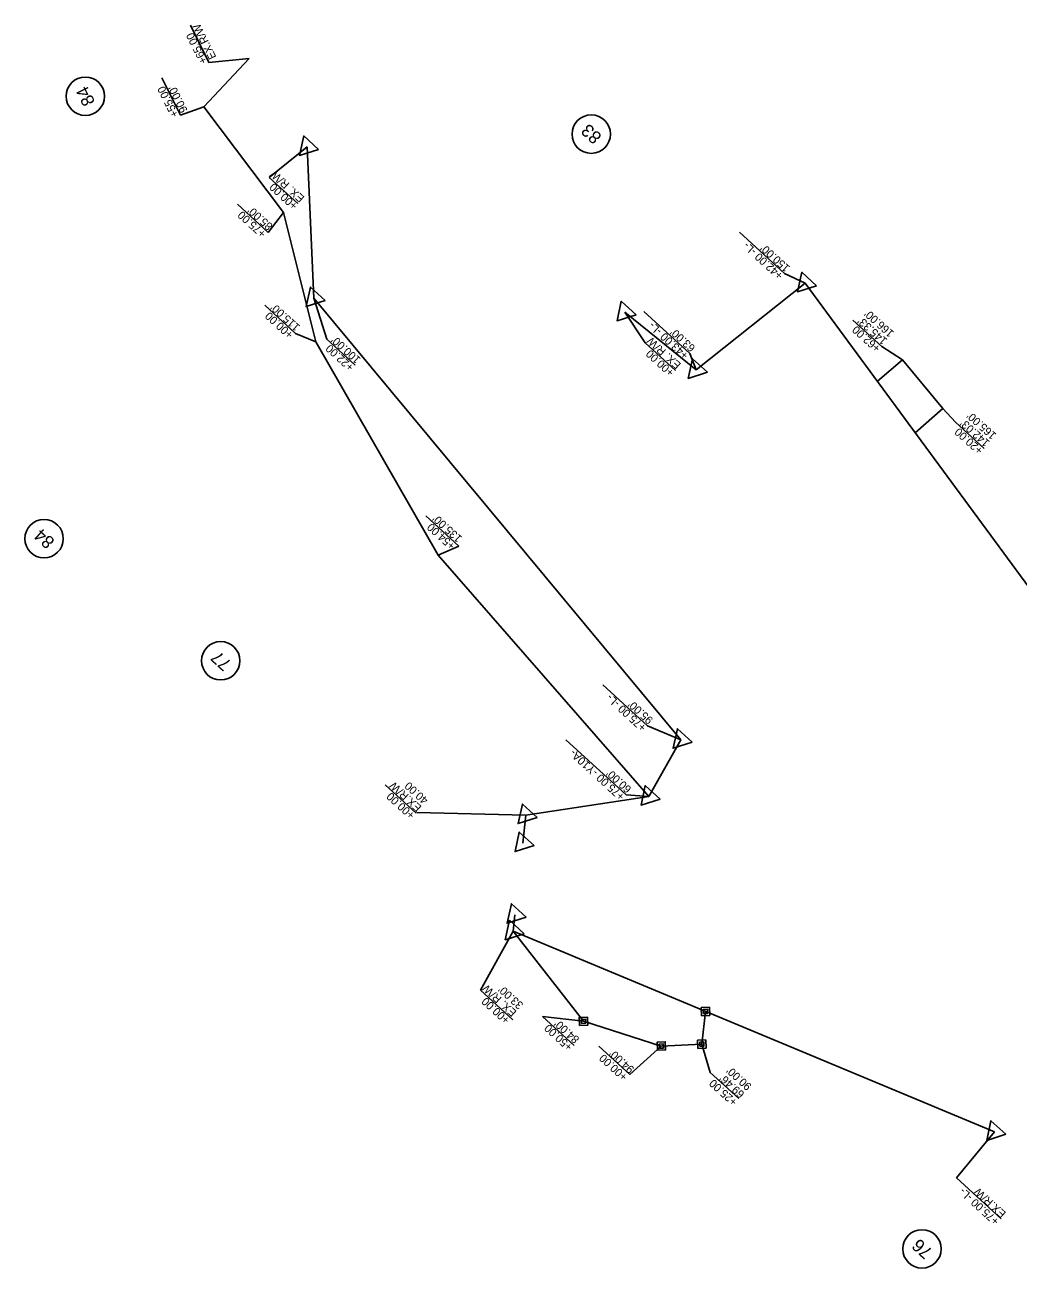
# Model space of a CAD drawing. Extents: x 474184 to 481900, y 489262 to 505659.
# Drawn here: x 476024 to 476644, y 500477 to 501253 of the extents above; entities that cross this region are included whole.
import ezdxf

# ---------------------------------------------------------------- set-up
doc = ezdxf.new("R2010")
doc.units = 0
for name, color, linetype in [('Prop Drainage Structure Drop Inlet Grate 2 Wide Slots and Sag Grates 840 22 CELL', 7, 'Continuous'), ('Prop Drainage Structure Pipe CSP 15in', 7, 'Continuous'), ('Prop Drainage Structure Pipe RCP 18in Class IV', 7, 'Continuous'), ('Prop Drainage Structure Pipe RCP 18in Class IV Label', 7, 'Continuous'), ('Prop Drainage Structure Pipe Side Drain 15in Label', 7, 'Continuous'), ('Prop Drainage Structure Pipe Stub Out CELL', 7, 'Continuous'), ('Prop Drainage Structure Plot Symbol 50 Scale', 7, 'Continuous'), ('Prop Earthen Structure False Sump CELL', 7, 'Continuous'), ('Prop Earthen Structure False Sump Label', 7, 'Continuous')]:
    doc.layers.add(name, color=color, linetype=linetype)

msp = doc.modelspace()

# ---------------------------------------------------------------- linework, layer by layer
at = {"layer": 'Prop Drainage Structure Drop Inlet Grate 2 Wide Slots and Sag Grates 840 22 CELL'}
for p, q in [((476372.78, 500631.1), (476328.73, 500687.32)), ((476446.66, 500616.85), (476448.93, 500637.26)), ((476421.37, 500615.64), (476372.78, 500631.1)), ((476446.66, 500616.85), (476421.37, 500615.64))]:
    msp.add_line(p, q, dxfattribs=at)
at = {"layer": 'Prop Drainage Structure Pipe CSP 15in'}
for p, q in [((476061.59, 501208.84), (476061.59, 501208.84)), ((476377.59, 501185.16), (476377.59, 501185.16)), ((476035.83, 500932.5), (476035.83, 500932.5)), ((476146.17, 500856.26), (476146.17, 500856.26)), ((476584.17, 500488.95), (476584.17, 500488.95))]:
    msp.add_line(p, q, dxfattribs=at)
for centre in [(476061.59, 501208.84), (476377.59, 501185.16), (476035.83, 500932.5), (476146.17, 500856.26), (476584.17, 500488.95)]:
    msp.add_circle(centre, 12, dxfattribs=at)
at = {"layer": 'Prop Drainage Structure Pipe RCP 18in Class IV'}
for p, q in [((476200.18, 501177.17), (476200.18, 501177.17)), ((476511.26, 501092.03), (476511.26, 501092.03)), ((476204.38, 501082.76), (476204.38, 501082.76)), ((476398.57, 501073.95), (476398.57, 501073.95)), ((476443.09, 501037.97), (476443.09, 501037.97)), ((476433.59, 500806.92), (476433.59, 500806.92)), ((476413.55, 500771.46), (476413.55, 500771.46)), ((476336.8, 500759.87), (476336.8, 500759.87)), ((476334.86, 500742.41), (476334.86, 500742.41)), ((476329.88, 500697.69), (476329.88, 500697.69)), ((476328.73, 500687.32), (476328.73, 500687.32)), ((476448.93, 500637.26), (476448.93, 500637.26)), ((476372.78, 500631.1), (476372.78, 500631.1)), ((476421.37, 500615.64), (476421.37, 500615.64)), ((476446.66, 500616.85), (476446.66, 500616.85)), ((476629.46, 500562.08), (476629.46, 500562.08))]:
    msp.add_line(p, q, dxfattribs=at)
for points in [[(476207.22, 501175.62), (476195.32, 501171.86), (476197.99, 501184.05)], [(476518.3, 501090.47), (476506.4, 501086.71), (476509.08, 501098.9)], [(476211.42, 501081.2), (476199.52, 501077.44), (476202.19, 501089.63)], [(476405.61, 501072.39), (476393.71, 501068.63), (476396.38, 501080.82)], [(476450.13, 501036.41), (476438.23, 501032.65), (476440.9, 501044.84)], [(476440.63, 500805.36), (476428.73, 500801.6), (476431.4, 500813.79)], [(476420.59, 500769.9), (476408.69, 500766.14), (476411.36, 500778.33)], [(476343.84, 500758.31), (476331.94, 500754.56), (476334.61, 500766.74)], [(476341.9, 500740.85), (476330, 500737.1), (476332.67, 500749.29)], [(476336.92, 500696.13), (476325.02, 500692.37), (476327.7, 500704.56)], [(476335.77, 500685.76), (476323.87, 500682), (476326.54, 500694.19)], [(476636.5, 500560.52), (476624.6, 500556.76), (476627.28, 500568.95)]]:
    msp.add_lwpolyline(points, close=True, dxfattribs=at)
at = {"layer": 'Prop Drainage Structure Pipe RCP 18in Class IV Label'}
for points in [[(476370.36, 500628.45), (476370.13, 500633.53), (476375.21, 500633.76), (476375.44, 500628.68)], [(476446.5, 500634.6), (476446.27, 500639.69), (476451.36, 500639.92), (476451.59, 500634.83)], [(476447.72, 500635.93), (476447.6, 500638.47), (476450.14, 500638.59), (476450.26, 500636.05)], [(476371.57, 500629.77), (476371.45, 500632.32), (476374, 500632.43), (476374.11, 500629.89)], [(476418.94, 500612.98), (476418.71, 500618.07), (476423.8, 500618.29), (476424.03, 500613.21)], [(476444.23, 500614.19), (476444, 500619.28), (476449.09, 500619.51), (476449.32, 500614.42)], [(476445.45, 500615.52), (476445.33, 500618.06), (476447.87, 500618.18), (476447.99, 500615.63)], [(476420.16, 500614.31), (476420.04, 500616.85), (476422.59, 500616.97), (476422.7, 500614.42)]]:
    msp.add_lwpolyline(points, close=True, dxfattribs=at)
at = {"layer": 'Prop Drainage Structure Pipe Side Drain 15in Label'}
for p, q in [((476204.38, 501082.76), (476200.18, 501177.17)), ((476511.26, 501092.03), (476443.09, 501037.97)), ((476740.27, 500780.72), (476511.26, 501092.03)), ((476433.59, 500806.92), (476204.38, 501082.76)), ((476398.57, 501073.95), (476443.09, 501037.97)), ((476413.55, 500771.46), (476433.59, 500806.92)), ((476413.55, 500771.46), (476336.8, 500759.87)), ((476334.86, 500742.41), (476336.8, 500759.87)), ((476328.73, 500687.32), (476329.88, 500697.69)), ((476629.46, 500562.08), (476328.73, 500687.32))]:
    msp.add_line(p, q, dxfattribs=at)
at = {"layer": 'Prop Drainage Structure Pipe Stub Out CELL'}
for p, q in [((476135.58, 501202.12), (476163.83, 501232.42)), ((476185.36, 501136.21), (476135.58, 501202.12)), ((476205.5, 501055.47), (476185.36, 501136.21)), ((476282.06, 500922.22), (476205.5, 501055.47)), ((476571.98, 501044.26), (476556.3, 501030.8)), ((476597.23, 501013.78), (476571.98, 501044.26)), ((476580.02, 500998.56), (476597.23, 501013.78)), ((476413.55, 500771.46), (476282.06, 500922.22))]:
    msp.add_line(p, q, dxfattribs=at)
at = {"layer": 'Prop Drainage Structure Plot Symbol 50 Scale'}
for p, q in [((476176.52, 501158.1), (476200.18, 501177.17)), ((476176.52, 501158.1), (476194.27, 501141.88)), ((476470.12, 501123.93), (476498.36, 501098.12)), ((476212.49, 501057.03), (476204.38, 501082.76)), ((476411.31, 501054.75), (476398.57, 501073.95)), ((476410.52, 501074.31), (476439.2, 501048.1)), ((476212.49, 501057.03), (476230.24, 501040.81)), ((476411.31, 501054.75), (476430.24, 501037.45)), ((476439.2, 501048.1), (476443.09, 501037.97)), ((476384.76, 500841.33), (476412.83, 500815.67)), ((476361.72, 500806.93), (476399.31, 500772.58)), ((476248.94, 500778.87), (476268.33, 500761.15)), ((476308.37, 500650.6), (476328.67, 500632.05)), ((476605.7, 500533.27), (476629.46, 500562.08)), ((476605.7, 500533.27), (476633.69, 500507.69))]:
    msp.add_line(p, q, dxfattribs=at)
for points in [[(476498.36, 501098.12), (476511.26, 501092.03)], [(476412.83, 500815.67), (476433.59, 500806.92)], [(476399.31, 500772.58), (476413.55, 500771.46)], [(476268.62, 500761.47), (476336.8, 500759.87)], [(476308.37, 500650.6), (476328.73, 500687.32)]]:
    msp.add_lwpolyline(points, dxfattribs=at)
at = {"layer": 'Prop Earthen Structure False Sump CELL'}
for p, q in [((476347.22, 500634.1), (476367.03, 500615.99)), ((476382.3, 500615.54), (476401.72, 500597.8)), ((476401.72, 500597.8), (476421.37, 500615.64)), ((476451.83, 500599.18), (476446.66, 500616.85)), ((476451.83, 500599.18), (476469.68, 500582.87))]:
    msp.add_line(p, q, dxfattribs=at)
msp.add_lwpolyline([(476347.22, 500634.1), (476372.78, 500631.1)], dxfattribs=at)
at = {"layer": 'Prop Earthen Structure False Sump Label'}
for p, q in [((476127.24, 501253.27), (476138.83, 501229.97)), ((476163.83, 501232.42), (476138.83, 501229.97)), ((476109.4, 501220.32), (476120.99, 501197.02)), ((476120.99, 501197.02), (476135.58, 501202.12)), ((476156.58, 501141.36), (476175.79, 501123.8)), ((476185.36, 501136.21), (476175.79, 501123.8)), ((476173.65, 501078.31), (476192.86, 501060.75)), ((476559.07, 501052.59), (476541.04, 501069.06)), ((476205.5, 501055.47), (476192.86, 501060.75)), ((476571.98, 501044.26), (476559.07, 501052.59)), ((476597.23, 501013.78), (476605.03, 501005.28)), ((476623.06, 500988.8), (476605.03, 501005.28)), ((476274.3, 500946.69), (476294.98, 500927.8)), ((476294.98, 500927.8), (476282.06, 500922.22))]:
    msp.add_line(p, q, dxfattribs=at)

# ---------------------------------------------------------------- texts
at = {"layer": 'Prop Drainage Structure Pipe CSP 15in'}
for s, rotation, p in [('84', 116.44074, (476067.86, 501205.21)), ('83', 137.57996, (476384.66, 501184.13)), ('84', 137.57996, (476042.99, 500931.38)), ('77', 137.57996, (476153.39, 500855.08)), ('76', 137.71823, (476591.31, 500487.86))]:
    msp.add_text(s, height=8, rotation=rotation, dxfattribs=at).set_placement(p)
at = {"layer": 'Prop Drainage Structure Plot Symbol 50 Scale'}
for s, p in [('EX. R/W', (476198.86, 501145.72)), ('+00.00', (476194.64, 501141.11)), ('+42.00 -L-', (476497.83, 501097.54)), ("150.00'", (476502.05, 501102.16)), ('+43.00 -L-', (476438.78, 501047.64)), ("63.00'", (476443, 501052.25)), ('+22.00', (476229.76, 501040.29)), ("100.00'", (476233.97, 501044.9)), ('EX. R/W', (476434.03, 501041.6)), ('+00.00', (476429.82, 501036.99)), ('+75.00 -L-', (476412.41, 500815.21)), ("95.00'", (476416.62, 500819.82)), ('+75.00 -Y10A-', (476398.89, 500772.12)), ('EX.R/W ', (476271.99, 500765.16)), ('40.00', (476276.21, 500769.77)), ("60.00'", (476403.1, 500776.73)), ('+00.00', (476267.78, 500760.54)), ('EX. R/W', (476331.38, 500637.18)), ("33.00'", (476335.6, 500641.79)), ('+00.00', (476327.17, 500632.57)), ('+75.00 -L-', (476632.83, 500506.89)), ('EX.R/W', (476637.05, 500511.51))]:
    msp.add_text(s, height=5, rotation=137.57996, dxfattribs=at).set_placement(p)
at = {"layer": 'Prop Earthen Structure False Sump CELL'}
for s, p in [('+50.00', (476366.33, 500615.79)), ("84.00'", (476370.55, 500620.4)), ('+00.00', (476400.65, 500597.11)), ("94.00'", (476404.86, 500601.73)), ("90.00'", (476478.15, 500591.07)), ('+25.00', (476469.31, 500581.39)), ("69.46'", (476473.73, 500586.23))]:
    msp.add_text(s, height=5, rotation=137.57996, dxfattribs=at).set_placement(p)
at = {"layer": 'Prop Earthen Structure False Sump Label'}
for s, rotation, p in [('+65.00', 116.44074, (476137.95, 501230.57)), ('EX.R/W', 116.44074, (476143.55, 501233.35)), ('+55.00', 116.44074, (476120.04, 501197.22)), ("90.00'", 116.44074, (476125.64, 501200)), ("85.00'", 137.57996, (476179.05, 501128.26)), ('+75.00', 137.57996, (476174.83, 501123.65)), ("115.00'", 137.57996, (476196.12, 501065.21)), ('+00.00', 137.57996, (476191.9, 501060.6)), ("145.33'", 138.10415, (476562.89, 501056.77)), ("166.00'", 138.10415, (476567.06, 501061.42)), ('+62.00', 138.10415, (476558.72, 501052.12)), ("142.03'", 138.10415, (476626.88, 500992.98)), ("165.00'", 138.10415, (476631.05, 500997.63)), ('+20.00', 138.10415, (476622.71, 500988.33)), ("135.00'", 137.57996, (476297.28, 500933.31)), ('+54.00', 137.57996, (476293.07, 500928.7))]:
    msp.add_text(s, height=5, rotation=rotation, dxfattribs=at).set_placement(p)

doc.saveas('drawing.dxf')
